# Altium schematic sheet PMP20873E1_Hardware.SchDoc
size 431 x 279 mm; Date: Not shown in title block; ApprovedBy: Not shown in title block; CheckedBy: Not shown in title block; Author: Not shown in title block; CompanyName: Not shown in title block; Engineer: Not shown in title block; Organization: Not shown in title block; Address1: Not shown in title block; Address2: Not shown in title block; Address3: Not shown in title block; Address4: Not shown in title block; DocumentNumber: 1; Revision: Use project parameter SCH_Rev; SheetNumber: 3; SheetTotal: 3; PageSetup: Record=PageOptions¦CenterHorizontal=True¦CenterVertical=True¦PrintScale=1.00¦XCorrection=1.00¦YCorrection=1.00¦PrintKind=0¦BorderSize=5000000¦LeftOffset=0¦BottomOffset=0¦Orientation=2¦PaperLength=1000¦PaperWidth=1000¦Scale=100¦PaperSource=15¦PrintQuality=600¦MediaType=1¦DitherType=10¦PaperKind=Letter¦PrintScaleMode=1
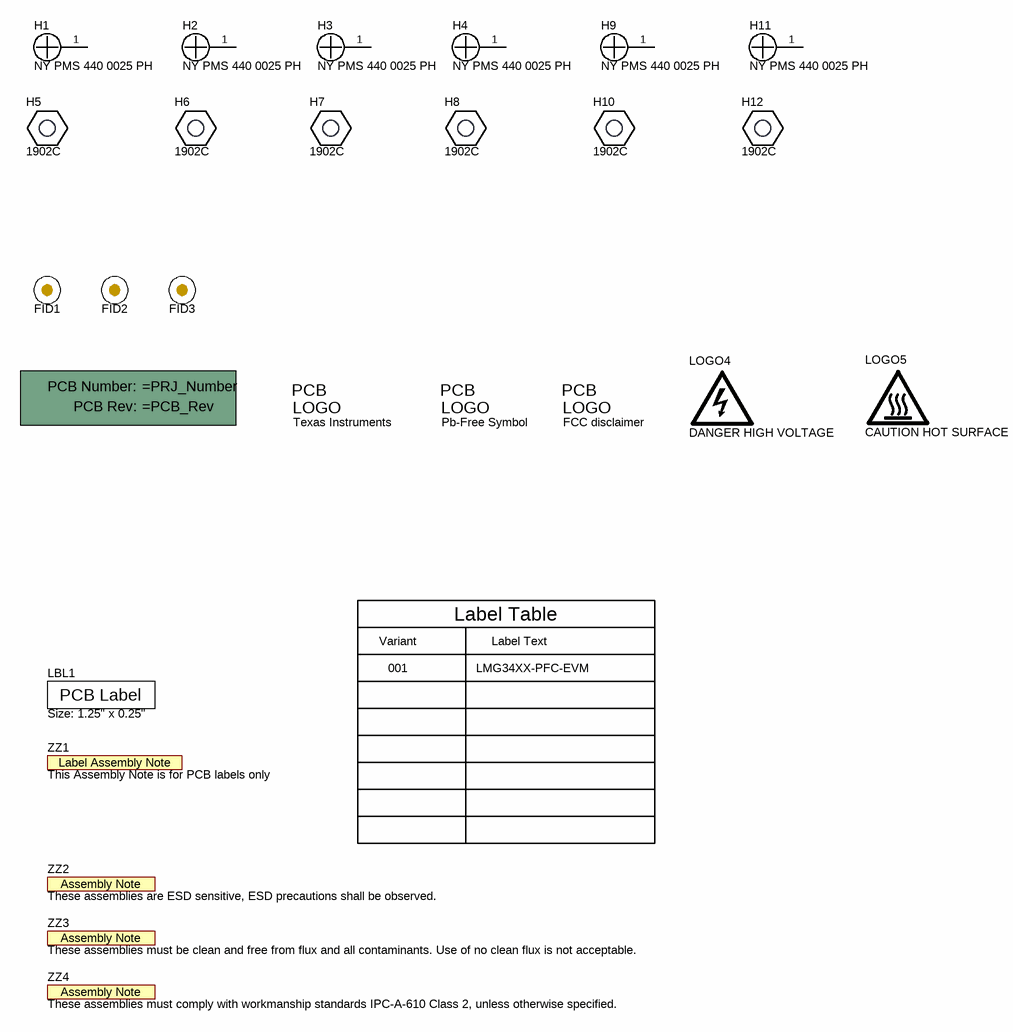
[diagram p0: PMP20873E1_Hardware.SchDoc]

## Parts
!PCB  Printed Circuit Board  (value not drawn)  (mechanical)
FID1  Fiducial  [Fiducial10-20]  (value not drawn)
FID2  Fiducial  [Fiducial10-20]  (value not drawn)
FID3  Fiducial  [Fiducial10-20]  (value not drawn)
H1  NY PMS 440 0025 PH  [NY PMS 440 0025 PH]
H2  NY PMS 440 0025 PH  [NY PMS 440 0025 PH]
H3  NY PMS 440 0025 PH  [NY PMS 440 0025 PH]
H4  NY PMS 440 0025 PH  [NY PMS 440 0025 PH]
H5  1902C  [Keystone_1902C]
H6  1902C  [Keystone_1902C]
H7  1902C  [Keystone_1902C]
H8  1902C  [Keystone_1902C]
H9  NY PMS 440 0025 PH  [NY PMS 440 0025 PH]
H10  1902C  [Keystone_1902C]
H11  NY PMS 440 0025 PH  [NY PMS 440 0025 PH]
H12  1902C  [Keystone_1902C]
LBL1  Size: 1.25" x 0.25"  [Label_1250x250]
Logo1  Texas Instruments  [TI_Stacked_Overlay_Small]  (no BOM)
Logo2  Pb-Free Symbol  [Pb-Free_Overlay_Small]  (no BOM)
Logo3  FCC disclaimer  [FCC_disclaimer]  (no BOM)
LOGO4  DANGER HIGH VOLTAGE  [IEC_HighVoltage_Small]  (no BOM)
LOGO5  CAUTION HOT SURFACE  [IEC_HotSurface_Small]  (no BOM)
ZZ1  This Assembly Note is for PCB labels only  [AssemblyNoteLabel]  (no BOM)
ZZ2  These assemblies are ESD sensitive, ESD precautions shall be observed.  [AssemblyNote]  (no BOM)
ZZ3  These assemblies must be clean and free from flux and all contaminants. Use of no clean flux is not acceptable.  [AssemblyNote]  (no BOM)
ZZ4  These assemblies must comply with workmanship standards IPC-A-610 Class 2, unless otherwise specified.  [AssemblyNote]  (no BOM)

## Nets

Not connected (* = marked no-connect by the designer): H1 1; H2 1; H3 1; H4 1; H9 1; H11 1

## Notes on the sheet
- Variant
- Label Table
- Label Text
- 001
- LMG34XX-PFC-EVM

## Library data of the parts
!PCB = PCB: Manufacturer: Any; SymbolCreator: a0412235
FID1-FID3 = Fiducial: Fiducial mark.  There is nothing to buy or mount.; SymbolCreator: codlsc
H1-H4 H9 H11 = NY PMS 440 0025 PH: Machine Screw, Round, #4-40 x 1/4, Nylon, Philips panhead; Manufacturer: B&F Fastener Supply; CompType: Hardware; SymbolCreator: codlsc; U/M: EA
H5-H8 H10 H12 = 1902C: Standoff, Hex, 0.5"L #4-40 Nylon; Manufacturer: Keystone; CompType: Hardware
LBL1 = THT-13-457-10: Thermal Transfer Printable Labels, 1.250" W x 0.250" H - 10,000 per roll; Manufacturer: Brady; SymbolCreator: a0412235; CompType: Label
Logo1 = TI_Logo: Texas Instrument Corporate Signature; SymbolCreator: codlsc
Logo2 = Pb-Free: SymbolCreator: a0412235
Logo3 = FCC_disclaimer: SymbolCreator: codlsc
LOGO4 = IEC_HighVoltage: IEC 61010-1 High Voltage Warning; SymbolCreator: a0412235
LOGO5 = IEC_HotSurface: IEC 61010-1 Hot Surface Warning; SymbolCreator: a0412235
ZZ1 = AssemblyNoteLabel: SymbolCreator: a0412235
ZZ2-ZZ4 = AssemblyNote: SymbolCreator: codlsc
